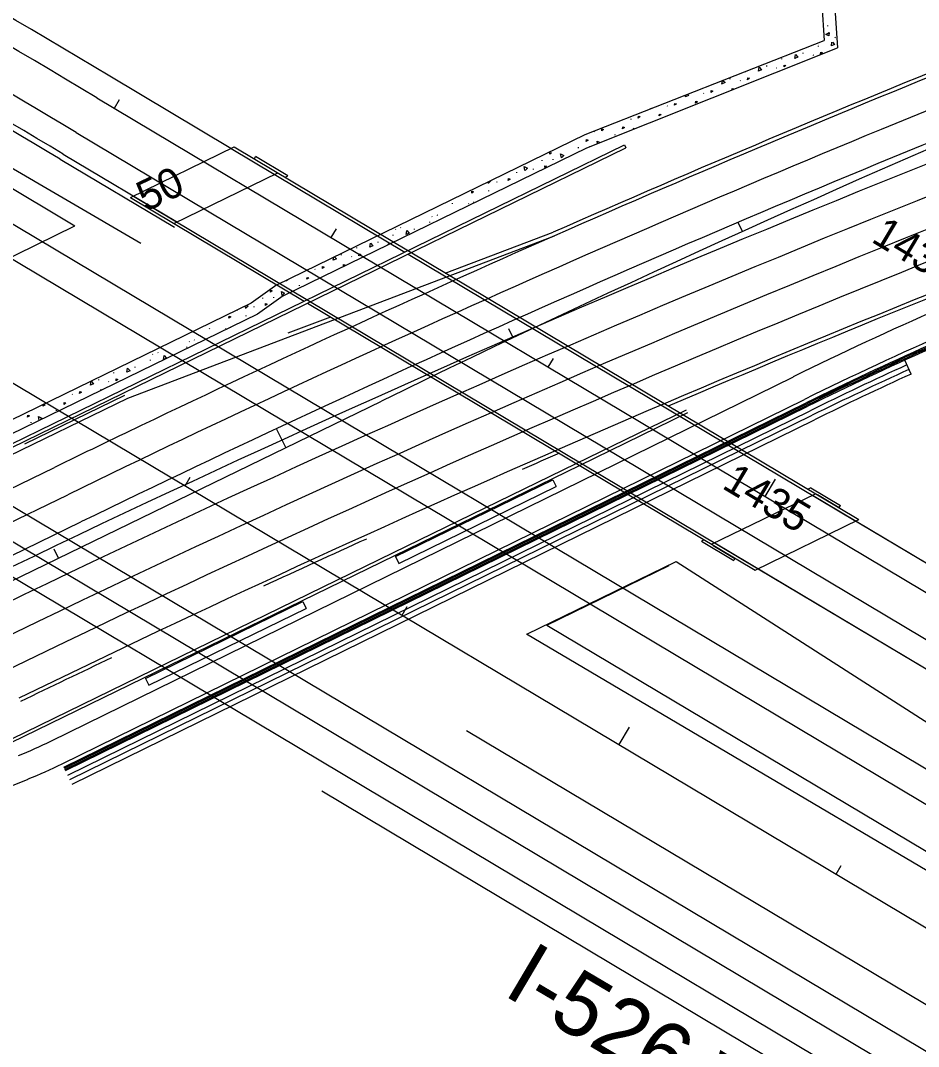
# Model space of a CAD drawing. Extents: x 2338610 to 2351914, y 366540 to 376484.
# Drawn here: x 2349298.6 to 2349654, y 367824.6 to 368230.7 of the extents above; entities that cross this region are included whole.
import ezdxf

# ---------------------------------------------------------------- set-up
doc = ezdxf.new("R2010")
doc.units = 0
for name, color, linetype in [('RD_HC_Cl', 7, 'Continuous'), ('RD_HC_CL_Rel', 7, 'Continuous'), ('RD_PD_Bridge', 7, 'Continuous'), ('RD_PD_Final_LnLine', 7, 'Continuous'), ('RD_PD_Final_TrvlWay', 7, 'Continuous'), ('RD_PD_FOC', 7, 'Continuous'), ('RD_PD_GR', 7, 'Continuous'), ('RD_PD_GrRail', 7, 'Continuous'), ('RD_PD_MedBWall', 7, 'Continuous'), ('RD_PD_PaveShd', 7, 'Continuous'), ('RD_PD_SW', 7, 'Continuous'), ('RD_PD_WallCut', 7, 'Continuous'), ('RD_PD_WallFill', 7, 'Continuous'), ('TR SN UNASSIGNED 4', 7, 'Continuous'), ('TR SN UNASSIGNED 7', 7, 'Continuous')]:
    doc.layers.add(name, color=color, linetype=linetype)

msp = doc.modelspace()

# ---------------------------------------------------------------- linework, layer by layer
at = {"layer": 'RD_HC_Cl'}
for p, q in [((2346281.57, 369885.43), (2351112.4, 367003.22)), ((2348794.11, 367765.14), (2349441.47, 368080.05))]:
    msp.add_line(p, q, dxfattribs=at)
msp.add_arc((2351947.82, 362927.74), 5729.58, 109.588035, 115.940729, dxfattribs=at)
at = {"layer": 'RD_HC_CL_Rel'}
msp.add_line((2349328.8, 368200.11), (2349775.06, 367933.86), dxfattribs=at)
msp.add_arc((2344717.52, 360471.2), 9000, 59.178507, 60.642806, dxfattribs=at)
at = {"layer": 'RD_PD_Bridge'}
for p, q in [((2349342.13, 368160.58), (2349383.21, 368180.61)), ((2349382, 368180.02), (2349450.75, 368139)), ((2349383.21, 368180.61), (2349630.39, 368033.13)), ((2349391.15, 368175.95), (2349391.66, 368176.8)), ((2349404.43, 368169.18), (2349391.66, 368176.8)), ((2349359.3, 368150.33), (2349400.39, 368170.36)), ((2349403.29, 368168.63), (2349404.43, 368169.18)), ((2349342.13, 368160.58), (2349410.89, 368119.55)), ((2349343.33, 368161.17), (2349590.52, 368013.69)), ((2349452.04, 368138.23), (2349629.18, 368032.54)), ((2349412.17, 368118.79), (2349589.31, 368013.1)), ((2349446.98, 368018.49), (2349509.32, 368048.89)), ((2349509.32, 368048.89), (2349510.63, 368046.19)), ((2349448.3, 368015.8), (2349510.63, 368046.19)), ((2349611.45, 368045.67), (2349610.31, 368045.11)), ((2349611.45, 368045.67), (2349623.1, 368038.72)), ((2349572.13, 368023.35), (2349613.22, 368043.38)), ((2349613.97, 368043), (2349622.59, 368037.86)), ((2349622.59, 368037.86), (2349623.1, 368038.72)), ((2349589.31, 368013.1), (2349630.39, 368033.13)), ((2349569.23, 368025.09), (2349568.08, 368024.53)), ((2349568.08, 368024.53), (2349580.86, 368016.91)), ((2349572.75, 368022.91), (2349581.37, 368017.76)), ((2349446.98, 368018.49), (2349448.3, 368015.8)), ((2349581.37, 368017.76), (2349580.86, 368016.91)), ((2349348.09, 367970.27), (2349410.38, 368000.65)), ((2349410.38, 368000.65), (2349411.7, 367997.95)), ((2349349.4, 367967.58), (2349411.7, 367997.95)), ((2349348.09, 367970.27), (2349349.4, 367967.58))]:
    msp.add_line(p, q, dxfattribs=at)
at = {"layer": 'RD_PD_Final_LnLine'}
for p, q in [((2348620.92, 368538.62), (2349820.78, 367822.75)), ((2349253.37, 368063.47), (2351090.88, 366967.15)), ((2349241.51, 368056.57), (2349846.26, 367695.75)), ((2348932.13, 367868.98), (2349312.02, 368053.77)), ((2348784.92, 367784.02), (2349317.27, 368042.98)), ((2348790.17, 367773.23), (2349322.52, 368032.19))]:
    msp.add_line(p, q, dxfattribs=at)
for centre, radius, start, end in [((2351783.35, 362853.29), 5729.58, 109.588035, 115.940729), ((2351783.35, 362853.29), 5717.58, 109.58804, 115.94073), ((2351783.35, 362853.29), 5705.58, 109.58804, 115.94073), ((2351828.87, 362879.88), 5741.58, 111.915714, 115.940729), ((2351783.35, 362853.29), 5693.58, 110.25944, 115.94073), ((2351828.87, 362879.88), 5729.58, 111.915714, 115.940729), ((2351828.87, 362879.88), 5753.58, 113.768054, 115.561063), ((2351828.87, 362879.88), 5753.58, 115.561063, 115.940729)]:
    msp.add_arc(centre, radius, start, end, dxfattribs=at)
at = {"layer": 'RD_PD_Final_TrvlWay'}
for p, q in [((2348626.93, 368549.01), (2349813.16, 367841.27)), ((2349328.8, 368200.11), (2349775.06, 367933.86)), ((2349320.61, 368186.37), (2349785.22, 367909.17)), ((2349341.05, 368081.24), (2349509.98, 368145.47)), ((2349008.27, 367919.36), (2349341.05, 368081.24)), ((2349229.65, 368049.67), (2349840.11, 367685.45))]:
    msp.add_line(p, q, dxfattribs=at)
for centre, radius, start, end in [((2344717.52, 360471.2), 9000, 59.178507, 60.642806), ((2344717.52, 360471.2), 8984, 59.178507, 60.415096), ((2351828.87, 362879.88), 5753.58, 111.915714, 113.768054), ((2351783.35, 362853.29), 5681.58, 111.03168, 115.94073)]:
    msp.add_arc(centre, radius, start, end, dxfattribs=at)
at = {"layer": 'RD_PD_FOC'}
for p, q in [((2349466.73, 368130.63), (2349509.44, 368146.87)), ((2349404.58, 368107), (2349421.43, 368113.41)), ((2349300.37, 368063.12), (2349339.83, 368082.31))]:
    msp.add_line(p, q, dxfattribs=at)
for centre, radius, start, end in [((2351828.87, 362879.88), 5755.08, 111.915714, 113.768054), ((2351783.35, 362853.29), 5680.08, 111.03168, 113.09877), ((2351783.35, 362853.29), 5680.08, 113.57163, 113.73484), ((2351783.35, 362853.29), 5680.08, 114.4154, 114.86723), ((2351783.35, 362853.29), 5680.08, 115.53838, 115.94073)]:
    msp.add_arc(centre, radius, start, end, dxfattribs=at)
at = {"layer": 'RD_PD_GR'}
for p, q in [((2349333.93, 368208.7), (2349381.89, 368180.08)), ((2349621.98, 368036.84), (2349768.71, 367949.3)), ((2349590.52, 368013.69), (2349791.57, 367893.74))]:
    msp.add_line(p, q, dxfattribs=at)
msp.add_arc((2344717.52, 360471.2), 9010, 59.178507, 60.642806, dxfattribs=at)
at = {"layer": 'RD_PD_GrRail'}
for p, q in [((2349142.77, 368261.41), (2349346.2, 368142.48)), ((2349558.12, 368016.57), (2349759.86, 367887.11)), ((2349769.99, 367827.67), (2349498.86, 367987.72))]:
    msp.add_line(p, q, dxfattribs=at)
at = {"layer": 'RD_PD_MedBWall'}
for p, q in [((2349235.32, 368033.93), (2349537.7, 368181.41)), ((2349235.87, 368032.8), (2349538.23, 368180.27)), ((2349537.7, 368181.41), (2349538.23, 368180.27)), ((2349518.54, 368055.33), (2349562.12, 368076.58)), ((2349519.82, 368054.56), (2349562.67, 368075.45)), ((2349446.22, 368020.07), (2349518.54, 368055.33)), ((2349446.77, 368018.94), (2349519.82, 368054.56)), ((2349257.43, 367928.02), (2349446.22, 368020.07)), ((2349257.98, 367926.9), (2349446.77, 368018.94))]:
    msp.add_line(p, q, dxfattribs=at)
at = {"layer": 'RD_PD_PaveShd'}
for p, q in [((2348633, 368559.35), (2349320.08, 368149.43)), ((2349333.93, 368208.7), (2349381.89, 368180.08)), ((2349315.48, 368177.79), (2349360.7, 368150.81)), ((2349277.31, 368128.37), (2349320.08, 368149.43)), ((2349612.02, 368042.78), (2349768.71, 367949.3)), ((2349573.34, 368023.94), (2349791.57, 367893.74)), ((2349498.97, 367987.72), (2349558.12, 368016.57)), ((2349506.94, 367991.36), (2349555.29, 368014.89)), ((2349506.94, 367991.36), (2350200.36, 367577.64)), ((2349475.16, 367949.69), (2350173.67, 367533.02)), ((2349417.91, 367925.7), (2349835.16, 367676.76))]:
    msp.add_line(p, q, dxfattribs=at)
for radius, end in [(9010, 60.642806), (8974, 60.415096)]:
    msp.add_arc((2344717.52, 360471.2), radius, 59.178507, end, dxfattribs=at)
at = {"layer": 'RD_PD_SW'}
for p, q in [((2349615.76, 368236.96), (2349616.72, 368222.79)), ((2349620.74, 368237.34), (2349621.94, 368219.82)), ((2349618, 368228.67), (2349618.01, 368228.47)), ((2349522.02, 368185.49), (2349616.72, 368222.79)), ((2349620.92, 368223.86), (2349621.14, 368224.02)), ((2349522.76, 368180.29), (2349621.94, 368219.82)), ((2349614.25, 368221.24), (2349614.25, 368221.25)), ((2349614.38, 368220.35), (2349614.4, 368220.62)), ((2349619.52, 368220.68), (2349619.73, 368222.04)), ((2349599.94, 368215.3), (2349599.96, 368215.57)), ((2349608.38, 368217.58), (2349608.4, 368217.85)), ((2349612.24, 368217.04), (2349612.4, 368216.92)), ((2349585.51, 368210.25), (2349585.53, 368210.51)), ((2349593.94, 368212.52), (2349593.97, 368212.8)), ((2349597.81, 368211.99), (2349597.96, 368211.87)), ((2349576.22, 368205.53), (2349576.43, 368206.92)), ((2349579.51, 368207.47), (2349579.53, 368207.74)), ((2349583.37, 368206.94), (2349583.53, 368206.82)), ((2349565.08, 368202.42), (2349565.08, 368202.45)), ((2349561.79, 368200.48), (2349561.9, 368201.2)), ((2349568.94, 368201.89), (2349569.1, 368201.77)), ((2349547.35, 368195.42), (2349547.36, 368195.47)), ((2349548.21, 368195.81), (2349547.38, 368195.43)), ((2349554.5, 368196.84), (2349554.66, 368196.72)), ((2349540.07, 368191.79), (2349540.23, 368191.67)), ((2349548.37, 368190.49), (2349548.37, 368190.58)), ((2349525.63, 368186.74), (2349525.79, 368186.62)), ((2349400.04, 368126.02), (2349522.02, 368185.49)), ((2349533.92, 368185.25), (2349533.94, 368185.53)), ((2349402.6, 368121.71), (2349522.76, 368180.29)), ((2349519.48, 368180.2), (2349519.5, 368180.47)), ((2349523.85, 368180.72), (2349523.86, 368180.79)), ((2349505.05, 368175.15), (2349505.07, 368175.42)), ((2349509.4, 368175.47), (2349509.43, 368175.74)), ((2349515.86, 368176.99), (2349515.89, 368176.94)), ((2349490.61, 368170.1), (2349490.62, 368170.18)), ((2349494.97, 368170.42), (2349494.99, 368170.69)), ((2349501.43, 368171.94), (2349501.53, 368171.71)), ((2349483.82, 368166.21), (2349483.7, 368166.81)), ((2349486.99, 368166.89), (2349487.1, 368166.66)), ((2349498.43, 368168.43), (2349498.44, 368168.49)), ((2349483.98, 368163.16), (2349484, 368163.44)), ((2349469.55, 368158.11), (2349469.57, 368158.38)), ((2349475.84, 368158.19), (2349476, 368158.07)), ((2349477.85, 368158.83), (2349478.01, 368158.71)), ((2349463.42, 368153.78), (2349463.58, 368153.66)), ((2349460.54, 368150.66), (2349460.56, 368150.93)), ((2349461.4, 368153.14), (2349461.56, 368153.02)), ((2349446.1, 368145.61), (2349446.13, 368145.88)), ((2349446.97, 368148.09), (2349447.13, 368147.97)), ((2349448.98, 368148.73), (2349449.14, 368148.61)), ((2349454.54, 368147.89), (2349454.56, 368148.16)), ((2349440.11, 368142.83), (2349440.13, 368143.11)), ((2349443.97, 368142.3), (2349444.13, 368142.18)), ((2349425.67, 368137.78), (2349425.69, 368138.05)), ((2349429.53, 368137.25), (2349429.69, 368137.13)), ((2349431.67, 368140.56), (2349431.69, 368140.83)), ((2349422.38, 368135.84), (2349422.56, 368137)), ((2349415.1, 368132.2), (2349415.26, 368132.08)), ((2349400.04, 368126.02), (2349389.83, 368118.81)), ((2349403.65, 368127.43), (2349403.69, 368127.8)), ((2349408.95, 368125.67), (2349408.97, 368125.94)), ((2349402.6, 368121.71), (2349392.39, 368114.49)), ((2349394.51, 368120.62), (2349394.53, 368120.89)), ((2349398.87, 368120.93), (2349398.89, 368121.21)), ((2349389.83, 368118.81), (2349003.02, 367930.15)), ((2349387.72, 368116.73), (2349387.52, 368117.68)), ((2349390.89, 368117.4), (2349391, 368117.18)), ((2349392.39, 368114.49), (2349005.21, 367925.65)), ((2349384.43, 368115.88), (2349384.46, 368116.16)), ((2349387.88, 368113.68), (2349387.9, 368113.95)), ((2349373.45, 368108.63), (2349373.47, 368108.9)), ((2349376.48, 368112.3), (2349376.57, 368112.13)), ((2349379.74, 368108.71), (2349379.9, 368108.59)), ((2349381.75, 368109.35), (2349381.79, 368109.32)), ((2349359.01, 368103.58), (2349359.03, 368103.78)), ((2349364.44, 368101.18), (2349364.46, 368101.45)), ((2349365.3, 368103.66), (2349365.46, 368103.54)), ((2349367.32, 368104.3), (2349367.48, 368104.18)), ((2349350.87, 368098.61), (2349351.03, 368098.49)), ((2349352.88, 368099.25), (2349353.04, 368099.12)), ((2349358.44, 368098.4), (2349358.46, 368098.67)), ((2349344.01, 368093.35), (2349344.03, 368093.62)), ((2349347.87, 368092.82), (2349347.9, 368092.79)), ((2349350, 368096.13), (2349350.03, 368096.4)), ((2349310.65, 367945.44), (2349604.47, 368089.68)), ((2349329.57, 368088.3), (2349329.59, 368088.57)), ((2349335.57, 368091.07), (2349335.59, 368091.35)), ((2349326.28, 368086.35), (2349326.52, 368087.93)), ((2349333.43, 368087.77), (2349333.59, 368087.65)), ((2349315.06, 367936.47), (2349608.87, 368080.7)), ((2349319, 368082.72), (2349319.16, 368082.6)), ((2349312.85, 368076.18), (2349312.87, 368076.46)), ((2349302.77, 368071.45), (2349302.79, 368071.72)), ((2348973.08, 367796.86), (2349301.62, 367930.44))]:
    msp.add_line(p, q, dxfattribs=at)
for points in [[(2349617.32, 368225.14), (2349618.69, 368225.97), (2349618.52, 368224.55), (2349617.34, 368225.12)], [(2349619.95, 368222.07), (2349620.75, 368221.23), (2349619.55, 368220.69)], [(2349605.09, 368215.63), (2349605.33, 368217.21), (2349606.31, 368216.18), (2349605.12, 368215.64)], [(2349615.23, 368217.33), (2349615.31, 368218.09), (2349615.97, 368217.88), (2349615.23, 368217.33)], [(2349590.66, 368210.58), (2349590.9, 368212.16), (2349591.88, 368211.12), (2349590.68, 368210.59)], [(2349600.79, 368212.27), (2349600.88, 368213.04), (2349601.54, 368212.83), (2349600.79, 368212.27)], [(2349576.58, 368206.98), (2349577.44, 368206.07), (2349576.25, 368205.54)], [(2349586.36, 368207.22), (2349586.44, 368207.99), (2349587.11, 368207.78), (2349586.36, 368207.22)], [(2349571.92, 368202.17), (2349572.01, 368202.94), (2349572.67, 368202.73), (2349571.92, 368202.17)], [(2349580.23, 368203.2), (2349580.29, 368203.73), (2349580.96, 368203.52), (2349580.84, 368203.44)], [(2349562.58, 368201.47), (2349563.01, 368201.02), (2349561.81, 368200.49)], [(2349565.77, 368197.92), (2349565.86, 368198.68), (2349566.52, 368198.47), (2349565.77, 368197.92)], [(2349557.49, 368197.12), (2349557.58, 368197.88), (2349558.24, 368197.68), (2349557.49, 368197.12)], [(2349543.06, 368192.07), (2349543.14, 368192.83), (2349543.8, 368192.62), (2349543.06, 368192.07)], [(2349551.34, 368192.87), (2349551.43, 368193.63), (2349552.09, 368193.42), (2349551.34, 368192.87)], [(2349528.62, 368187.02), (2349528.71, 368187.78), (2349529.37, 368187.57), (2349528.62, 368187.02)], [(2349536.91, 368187.81), (2349536.99, 368188.58), (2349537.65, 368188.37), (2349536.91, 368187.81)], [(2349541.3, 368187.68), (2349541.24, 368187.99), (2349541.61, 368187.8)], [(2349522.47, 368182.76), (2349522.56, 368183.53), (2349523.22, 368183.32), (2349522.47, 368182.76)], [(2349527, 368181.98), (2349526.8, 368182.94), (2349527.95, 368182.36)], [(2349508.04, 368177.71), (2349508.12, 368178.48), (2349508.78, 368178.27), (2349508.04, 368177.71)], [(2349512.68, 368176.31), (2349512.37, 368177.88), (2349513.65, 368177.24), (2349512.71, 368176.33)], [(2349498.25, 368171.26), (2349497.93, 368172.83), (2349499.21, 368172.19), (2349498.27, 368171.28)], [(2349506.06, 368172.42), (2349506.15, 368173.18), (2349506.81, 368172.97), (2349506.06, 368172.42)], [(2349484.58, 368167.24), (2349484.78, 368167.14), (2349483.84, 368166.23)], [(2349491.63, 368167.37), (2349491.71, 368168.13), (2349492.37, 368167.92), (2349491.63, 368167.37)], [(2349477.19, 368162.32), (2349477.28, 368163.08), (2349477.94, 368162.87), (2349477.19, 368162.32)], [(2349451.25, 368145.94), (2349451.49, 368147.52), (2349452.47, 368146.49), (2349451.28, 368145.95)], [(2349436.82, 368140.89), (2349437.06, 368142.47), (2349438.04, 368141.43), (2349436.84, 368140.9)], [(2349422.87, 368137.16), (2349423.6, 368136.38), (2349422.41, 368135.85)], [(2349432.52, 368137.53), (2349432.61, 368138.3), (2349433.27, 368138.09), (2349432.52, 368137.53)], [(2349418.09, 368132.48), (2349418.17, 368133.25), (2349418.83, 368133.04), (2349418.09, 368132.48)], [(2349426.37, 368133.3), (2349426.46, 368134.04), (2349427.12, 368133.83), (2349426.44, 368133.33)], [(2349411.94, 368128.23), (2349412.02, 368128.99), (2349412.68, 368128.78), (2349411.94, 368128.23)], [(2349404.2, 368128.05), (2349404.4, 368127.99), (2349403.65, 368127.43)], [(2349416.27, 368128.38), (2349416.27, 368128.4), (2349416.3, 368128.39)], [(2349397.5, 368123.18), (2349397.59, 368123.94), (2349398.25, 368123.73), (2349397.5, 368123.18)], [(2349402.15, 368121.78), (2349401.83, 368123.35), (2349403.11, 368122.71), (2349402.17, 368121.8)], [(2349388.08, 368117.95), (2349388.68, 368117.66), (2349387.74, 368116.74)], [(2349395.53, 368117.88), (2349395.61, 368118.65), (2349396.27, 368118.44), (2349395.53, 368117.88)], [(2349381.09, 368112.83), (2349381.18, 368113.6), (2349381.84, 368113.39), (2349381.09, 368112.83)], [(2349355.15, 368096.46), (2349355.39, 368098.04), (2349356.37, 368097), (2349355.18, 368096.47)], [(2349340.72, 368091.41), (2349340.96, 368092.99), (2349341.94, 368091.95), (2349340.74, 368091.41)], [(2349336.42, 368088.05), (2349336.51, 368088.81), (2349337.17, 368088.6), (2349336.42, 368088.05)], [(2349326.53, 368087.93), (2349327.5, 368086.9), (2349326.31, 368086.36)], [(2349330.32, 368084.22), (2349330.36, 368084.56), (2349330.76, 368084.43)], [(2349321.99, 368083), (2349322.07, 368083.76), (2349322.73, 368083.55), (2349321.99, 368083)], [(2349307.55, 368077.95), (2349307.64, 368078.71), (2349308.3, 368078.5), (2349307.55, 368077.95)], [(2349315.84, 368078.74), (2349315.92, 368079.51), (2349316.58, 368079.3), (2349315.84, 368078.74)], [(2349301.4, 368073.69), (2349301.49, 368074.46), (2349302.15, 368074.25), (2349301.4, 368073.69)], [(2349306.04, 368072.37), (2349305.73, 368073.86), (2349307.01, 368073.22), (2349306.24, 368072.47)]]:
    msp.add_lwpolyline(points, dxfattribs=at)
for centre, radius, start, end in [((2350269.88, 366734.2), 1510, 111.30456, 116.14693), ((2350269.88, 366734.2), 1500, 111.30456, 116.14693), ((2349222.52, 368124.98), 200, 292.1267, 296.1469), ((2349222.52, 368124.98), 210, 292.1267, 296.1469)]:
    msp.add_arc(centre, radius, start, end, dxfattribs=at)
at = {"layer": 'RD_PD_WallCut'}
for p, q in [((2349315.48, 368177.79), (2349360.7, 368150.81)), ((2349314.29, 368175.78), (2349359.5, 368148.8))]:
    msp.add_line(p, q, dxfattribs=at)
for radius in [8974, 8971.67]:
    msp.add_arc((2344717.52, 360471.2), radius, 59.178507, 60.415096, dxfattribs=at)
at = {"layer": 'RD_PD_WallFill'}
for p, q in [((2349651.05, 368090.72), (2349648.56, 368096.17)), ((2349315.72, 367935.12), (2349609.53, 368079.36)), ((2349315.94, 367934.67), (2349609.75, 368078.91)), ((2349316.16, 367934.22), (2349609.97, 368078.46)), ((2349316.38, 367933.77), (2349610.19, 368078.01)), ((2349317.26, 367931.98), (2349611.08, 368076.21)), ((2349318.15, 367930.18), (2349611.96, 368074.42)), ((2349319.03, 367928.39), (2349612.84, 368072.62))]:
    msp.add_line(p, q, dxfattribs=at)
for radius, start in [(1498.5, 114.10151), (1498, 114.10151), (1497.5, 114.10151), (1497, 114.10151), (1495, 114.52218), (1493, 114.52218), (1491, 114.52218)]:
    msp.add_arc((2350269.88, 366734.2), radius, start, 116.14693, dxfattribs=at)
at = {"layer": 'TR SN UNASSIGNED 7'}
for p, q in [((2349335.73, 368195.98), (2349337.78, 368199.42)), ((2349584.32, 368147.12), (2349582.67, 368150.77)), ((2349421.61, 368144.74), (2349423.66, 368148.18)), ((2349493.59, 368105.08), (2349491.88, 368108.69)), ((2349507.49, 368093.51), (2349509.53, 368096.94)), ((2349403.54, 368061.6), (2349400.04, 368068.79)), ((2349363.76, 368046.51), (2349365.8, 368049.95)), ((2349593.36, 368042.27), (2349597.46, 368049.14)), ((2349313.62, 368017.85), (2349311.87, 368021.45)), ((2349449.63, 367995.28), (2349451.68, 367998.71)), ((2349535.51, 367944.04), (2349539.61, 367950.91)), ((2349621.39, 367892.8), (2349623.44, 367896.24))]:
    msp.add_line(p, q, dxfattribs=at)

# ---------------------------------------------------------------- texts
at = {"layer": 'TR SN UNASSIGNED 4'}
msp.add_text('I-526 WEST', height=25, rotation=329.4094, dxfattribs=at).set_placement((2349489.08, 367845.27))
at = {"layer": 'TR SN UNASSIGNED 7'}
for s, rotation, p in [('50', 25.9407, (2349348.33, 368154.84)), ('1435', 329.1785, (2349634.86, 368143.28)), ('1435', 329.1785, (2349575.78, 368045.77))]:
    msp.add_text(s, height=12, rotation=rotation, dxfattribs=at).set_placement(p)

doc.saveas('drawing.dxf')
